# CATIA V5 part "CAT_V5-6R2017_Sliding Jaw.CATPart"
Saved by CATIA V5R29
Part number: Sliding Jaw
Bounding box of the stored display mesh (mm): x -32 to 32, y -16 to 16, z -9 to 36
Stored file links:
  E:\KAVITA\RESOURCES\CATIA_RESOURCES\Tutorial Files\Tutorials\Tutorials\c16_catia_v5_6r2018_tut\c16_catia_v5_6r2018_tut\c16_catia_v5_6r2018_tut\Bench vice\CAT_V5-6R2017_Sliding Jaw.CATPart
  C:\Program Files\Dassault Systemes\B09\intel_a\reffiles\standard\MetricThickPitch.txt
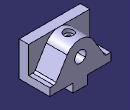
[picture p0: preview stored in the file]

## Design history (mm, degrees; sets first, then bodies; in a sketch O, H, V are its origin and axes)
Body1 (main body)
  Sketch1 on xy-plane, origin (0, 0, 0), H (1, 0, 0), V (0, 1, 0)
    line L1 (-32, -16) -> (32, -16)
    line L2 (32, -16) -> (32, 16)
    line L3 (32, 16) -> (-32, 16)
    line L4 (-32, 16) -> (-32, -16)
    distance H L1 = 16
    distance V L4 = 32
    length L4 = 32
    length L1 = 64
    horizontal: L1 H, L3 H
    vertical: L2 V, L4 V
  Pad1: profile Sketch1, direction (0, 0, 1), length 8
  Sketch2 on face of Pad1, origin (0, -16, 0), H (1, 0, 0), V (0, 0, 1)
    point P1 (-32, 0)
    line L1 (-32, 0) -> (32, 0)
    line L2 (32, 0) -> (32, 36)
    line L3 (32, 36) -> (-32, 36)
    line L4 (-32, 36) -> (-32, 0)
    reference projected line E1 (32, 0) -> (32, 8) from edge of Pad1
    reference projected line E2 (-32, 8) -> (-32, 0) from edge of Pad1
    length L2 = 36
    coincidence: P1 H, L2 E1, L4 E2
    horizontal: L1 H, L3 H
    vertical: L2 V, L4 V
  Pad2: profile Sketch2, direction (0, 1, 0), length 10
  Sketch3 on face of Pad1, origin (0, 16, 0), H (-1, 0, 0), V (0, 0, 1)
    arc A1 centre (0, 20) radius 16 from (13.6777, 28.3018) to (-13.6777, 28.3018) ccw
    point P1 (0, 20)
    reference projected line E1 (-32, 36) -> (32, 36) from edge of Pad2
    line L1 (-26, 8) -> (-13.6777, 28.3018)
    point P2 (-26, 8)
    line L2 (13.6777, 28.3018) -> (26, 8)
    point P3 (26, 8)
    reference projected line E2 (32, 8) -> (-32, 8) from edge of Pad1
    reference projected line E3 (32, 8) -> (-32, 8) from edge of Pad1
    line L3 (-26, 8) -> (26, 8)
    radius A1 = 16
    length L3 = 52
    distance V P3 = 26
    coincidence: P1 V, E2 P2, E3 P3
    tangency: A1 E1, L2 A1, L1 A1
    horizontal: L3 H
  Pad3: profile Sketch3, direction (0, -1, 0), up to the existing solid (limit type 2)
  Fillet1: radius 3, on 2 edges
  Sketch4 on face of Pad1, origin (-2.6964, 16, 22.8197), H (1, 0, 0), V (0, 0, -1)
    point P1 (2.6964, 2.8197)
    reference projected arc E1 centre (2.6964, 2.8197) radius 16 from (-10.9814, -5.4821) to (16.3741, -5.4821) ccw from edge of Pad3
    concentricity: P1 E1
  Hole1: placed by Sketch4, at (0, 16, 20) direction (0, -1, 0), diameter 12, depth 22, V-bottom angle 120
  Sketch5 on face of Pad1, origin (0, 16, 0), H (-1, 0, 0), V (0, 0, 1)
    point P1 (-7.75, 0)
    line L1 (-7.75, 0) -> (7.75, 0)
    line L2 (7.75, 0) -> (7.75, -9)
    line L3 (7.75, -9) -> (-7.75, -9)
    line L4 (-7.75, -9) -> (-7.75, 0)
    distance V L2 = 7.75
    length L3 = 15.5
    length L4 = 9
    coincidence: P1 H
    horizontal: L1 H, L3 H
    vertical: L2 V, L4 V
  Pad4: profile Sketch5, direction (0, -1, 0), length 32
  Sketch6 on face of Pad4, origin (-0.598, -1.2346, -9), H (1, 0, 0), V (0, -1, 0)
    point P1 (0.598, -9.2346)
    reference projected line E1 (8.348, -17.2346) -> (-7.152, -17.2346) from edge of Pad4
    reference projected line E2 (8.348, 14.7654) -> (8.348, -17.2346) from edge of Pad4
    distance P1 E1 = 8
    distance P1 E2 = 7.75
  Hole2: placed by Sketch6, at (0, 8, -9) direction (0, 0, 1), diameter 5, depth 16, V-bottom angle 120, threaded, thread diameter 6, thread depth 16, pitch 1
  RectPattern1: of Hole2, direction 1 instances 2, spacing 16, along edge of Pad4 reversed
  Sketch7 on face of Pad2, origin (-19.6018, -13.7351, 36), H (1, 0, 0), V (0, 1, 0)
    point P1 (19.6018, 17.7351)
    reference intersected line E1 through (19.6018, 0) direction (0, 1) from yz-plane
    reference projected line E2 (51.6018, -2.2649) -> (-12.3982, -2.2649) from edge of Pad2
    distance P1 E2 = 20
    coincidence: E1 P1
  Hole3: placed by Sketch7, at (0, 4, 36) direction (0, 0, -1), diameter 5, depth 16, V-bottom angle 120, counterbore diameter 10, counterbore depth 4, threaded, thread diameter 6, thread depth 11, pitch 1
